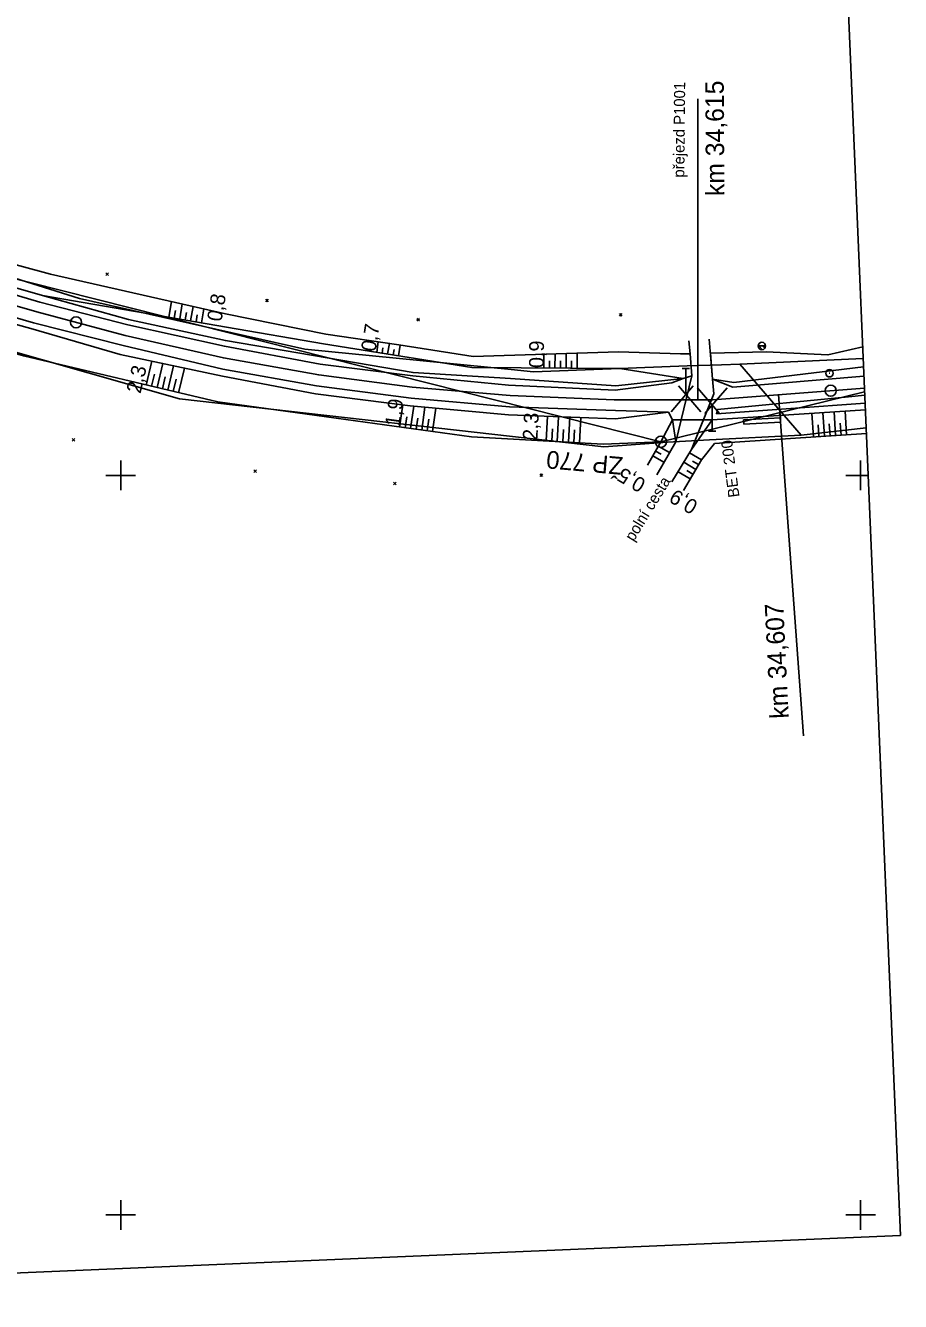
# Model space of a CAD drawing. Extents: x -806456 to -805395, y -1150847 to -1150506.
# Drawn here: x -805512.9 to -805394.6, y -1150811.7 to -1150639.2 of the extents above; entities that cross this region are included whole.
import ezdxf

# ---------------------------------------------------------------- set-up
doc = ezdxf.new("R2010")
doc.units = 0
for name, color, linetype in [('0381KM032-037P - Vrstva 1', 7, 'Continuous'), ('0381KM032-037P - Vrstva 19', 7, 'Continuous'), ('0381KM032-037P - Vrstva 36', 7, 'Continuous'), ('0381KM032-037P - Vrstva 4', 7, 'Continuous'), ('0381KM032-037P - Vrstva 48', 7, 'Continuous'), ('0381KM032-037P - Vrstva 49', 7, 'Continuous'), ('0381KM032-037P - Vrstva 51', 7, 'Continuous'), ('0381KM032-037P - Vrstva 55', 7, 'Continuous'), ('0381KM032-037P - Vrstva 7', 7, 'Continuous'), ('0381KM032-037P - Vrstva 9', 7, 'Continuous'), ('formát', 7, 'Continuous'), ('hran DP - hran DP', 7, 'Continuous'), ('krizky_1000 - Vrstva 1', 7, 'Continuous'), ('vyt_sit - polygon', 7, 'Continuous'), ('vyt_sit - stávající', 7, 'Continuous')]:
    doc.layers.add(name, color=color, linetype=linetype)

msp = doc.modelspace()

# ---------------------------------------------------------------- linework, layer by layer
at = {"layer": '0381KM032-037P - Vrstva 1'}
for points in [[(-805499.4, -1150681.08), (-805511.35, -1150677.89), (-805524.48, -1150674.12), (-805529.81, -1150672.54)], [(-805399.47, -1150688.2), (-805419.96, -1150689.78), (-805423.96, -1150689.8), (-805433.29, -1150689.8), (-805447.38, -1150689.21), (-805460.61, -1150688.07), (-805473.24, -1150686.41), (-805486.12, -1150684.11), (-805499.4, -1150681.08)]]:
    msp.add_lwpolyline(points, dxfattribs=at)
at = {"layer": '0381KM032-037P - Vrstva 19'}
msp.add_line((-805425.41, -1150692.47), (-805420.07, -1150692.47), dxfattribs=at)
at = {"layer": '0381KM032-037P - Vrstva 36'}
for p, q in [((-805413.84, -1150682.5), (-805412.84, -1150682.5)), ((-805412.84, -1150682.5), (-805413.84, -1150682.5)), ((-805413.28, -1150683), (-805413.77, -1150682.5)), ((-805412.94, -1150682.8), (-805413.24, -1150682.5))]:
    msp.add_line(p, q, dxfattribs=at)
msp.add_circle((-805413.34, -1150682.5), 0.503, dxfattribs=at)
msp.add_arc((-805413.34, -1150682.5), 0.503, 180, 0, dxfattribs=at)
at = {"layer": '0381KM032-037P - Vrstva 4'}
for p, q in [((-805421.99, -1150689.77), (-805421.99, -1150649.07)), ((-805423.11, -1150685.55), (-805424.11, -1150685.55)), ((-805423.61, -1150685.55), (-805423.61, -1150689.05)), ((-805422.61, -1150687.9), (-805425.61, -1150691.4)), ((-805421.61, -1150691.4), (-805424.61, -1150687.9)), ((-805422.05, -1150688.15), (-805419.05, -1150691.65)), ((-805421.05, -1150691.65), (-805418.05, -1150688.15)), ((-805423.96, -1150689.8), (-805419.82, -1150689.74)), ((-805420.05, -1150694), (-805420.05, -1150690.5)), ((-805420.55, -1150694), (-805419.55, -1150694))]:
    msp.add_line(p, q, dxfattribs=at)
for points in [[(-805485.85, -1150681.76), (-805498.96, -1150678.92), (-805510.6, -1150675.66), (-805525.22, -1150671.48), (-805544.53, -1150665.72), (-805562.31, -1150661.11), (-805574.56, -1150658.15), (-805590.74, -1150655.42), (-805602.22, -1150654.14), (-805617.62, -1150652.74), (-805630.08, -1150651.83), (-805647.65, -1150650.8), (-805688.26, -1150650.5)], [(-805423.97, -1150686.92), (-805425.51, -1150687.49), (-805433.17, -1150688.49), (-805447.58, -1150687.79), (-805460.54, -1150686.52), (-805473.03, -1150684.97), (-805486, -1150682.53), (-805499.06, -1150679.64), (-805510.93, -1150676.58), (-805525.41, -1150672.29), (-805545.14, -1150666.47), (-805562.36, -1150661.85), (-805574.71, -1150659.28), (-805590.7, -1150656.46), (-805602.42, -1150654.96), (-805617.57, -1150653.8), (-805630.08, -1150653.28), (-805647.6, -1150652.35), (-805687.98, -1150651.47)], [(-805425.98, -1150691.47), (-805433.13, -1150691.22), (-805447.47, -1150690.71), (-805460.74, -1150689.57), (-805473.54, -1150687.87), (-805486.2, -1150685.62), (-805499.7, -1150682.42), (-805511.82, -1150679.35), (-805526.11, -1150675.23), (-805545.84, -1150669.48), (-805563.16, -1150664.96), (-805575.57, -1150662.2), (-805590.62, -1150659.46), (-805602.86, -1150658.06), (-805617.64, -1150656.78), (-805630.16, -1150656.16), (-805647.73, -1150655.65), (-805688.15, -1150654.42)], [(-805425.41, -1150692.47), (-805425.98, -1150691.47), (-805433.11, -1150692.35), (-805447.61, -1150691.82), (-805460.9, -1150690.59), (-805473.67, -1150688.98), (-805486.26, -1150686.57), (-805500.08, -1150683.65), (-805512.15, -1150680.12), (-805526.27, -1150676.26), (-805545.98, -1150670.57), (-805563.42, -1150665.87), (-805575.79, -1150663.12), (-805590.93, -1150660.59), (-805603.28, -1150659.09), (-805617.92, -1150657.97), (-805630.11, -1150657.32), (-805646.66, -1150657.1), (-805648.58, -1150657.2), (-805687.42, -1150655.93)], [(-805423.97, -1150686.92), (-805433.1, -1150687.91), (-805447.34, -1150686.91), (-805460.49, -1150686.09), (-805485.85, -1150681.76)], [(-805399.6, -1150685.34), (-805417.14, -1150687.42), (-805420, -1150686.97)], [(-805399.54, -1150686.56), (-805417.27, -1150688.09), (-805420, -1150686.97)], [(-805399.43, -1150689.16), (-805401.63, -1150689.36), (-805419.33, -1150691.07), (-805419.49, -1150691.68)], [(-805399.39, -1150690.24), (-805419.49, -1150691.68)]]:
    msp.add_lwpolyline(points, dxfattribs=at)
at = {"layer": '0381KM032-037P - Vrstva 48'}
for p, q in [((-805493.52, -1150678.6), (-805493.15, -1150676.49)), ((-805492.78, -1150678.73), (-805492.6, -1150677.69)), ((-805492.04, -1150678.85), (-805491.69, -1150676.82)), ((-805491.3, -1150678.98), (-805491.13, -1150677.99)), ((-805490.56, -1150679.11), (-805490.22, -1150677.16)), ((-805489.82, -1150679.23), (-805489.66, -1150678.28)), ((-805489.08, -1150679.36), (-805488.76, -1150677.49)), ((-805465.41, -1150683.34), (-805465.19, -1150681.94)), ((-805464.67, -1150683.46), (-805464.56, -1150682.75)), ((-805463.93, -1150683.58), (-805463.7, -1150682.16)), ((-805463.19, -1150683.7), (-805463.07, -1150682.98)), ((-805462.45, -1150683.82), (-805462.22, -1150682.37)), ((-805441.32, -1150685.5), (-805441.3, -1150683.55)), ((-805439.82, -1150685.51), (-805439.8, -1150683.51)), ((-805438.32, -1150685.52), (-805438.3, -1150683.46)), ((-805496.56, -1150687.78), (-805495.8, -1150684.56)), ((-805495.1, -1150688.12), (-805494.33, -1150684.87)), ((-805493.64, -1150688.47), (-805492.86, -1150685.18)), ((-805442.82, -1150685.49), (-805442.8, -1150683.6)), ((-805442.07, -1150685.49), (-805442.06, -1150684.53)), ((-805440.57, -1150685.5), (-805440.56, -1150684.52)), ((-805439.07, -1150685.51), (-805439.06, -1150684.5)), ((-805495.83, -1150687.95), (-805495.45, -1150686.33)), ((-805494.37, -1150688.3), (-805493.98, -1150686.66)), ((-805492.91, -1150688.64), (-805492.52, -1150686.99)), ((-805492.18, -1150688.82), (-805491.39, -1150685.49)), ((-805462.31, -1150693.46), (-805461.89, -1150690.47)), ((-805461.56, -1150693.56), (-805461.35, -1150692.06)), ((-805460.82, -1150693.66), (-805460.4, -1150690.64)), ((-805459.33, -1150693.87), (-805458.91, -1150690.78)), ((-805457.85, -1150694.07), (-805457.41, -1150690.91)), ((-805442.5, -1150695.34), (-805442.32, -1150692.01)), ((-805441, -1150695.43), (-805440.82, -1150692.07)), ((-805439.5, -1150695.51), (-805439.32, -1150692.12)), ((-805438, -1150695.59), (-805437.82, -1150692.18)), ((-805406.38, -1150694.81), (-805406.59, -1150691.59)), ((-805404.88, -1150694.71), (-805405.09, -1150691.49)), ((-805403.39, -1150694.62), (-805403.59, -1150691.39)), ((-805401.89, -1150694.52), (-805402.09, -1150691.3)), ((-805460.08, -1150693.77), (-805459.86, -1150692.24)), ((-805458.59, -1150693.97), (-805458.38, -1150692.41)), ((-805441.75, -1150695.39), (-805441.66, -1150693.71)), ((-805440.25, -1150695.47), (-805440.16, -1150693.78)), ((-805438.75, -1150695.55), (-805438.66, -1150693.85)), ((-805405.63, -1150694.76), (-805405.73, -1150693.15)), ((-805404.13, -1150694.66), (-805404.24, -1150693.05)), ((-805402.64, -1150694.57), (-805402.74, -1150692.96)), ((-805428.08, -1150697.36), (-805426.58, -1150698.22)), ((-805427.71, -1150696.71), (-805426.96, -1150697.14)), ((-805427.34, -1150696.06), (-805425.83, -1150696.92)), ((-805421.51, -1150697.9), (-805423.11, -1150696.95)), ((-805422.27, -1150699.19), (-805423.9, -1150698.22)), ((-805421.89, -1150698.54), (-805422.7, -1150698.06)), ((-805423.04, -1150700.48), (-805424.68, -1150699.5)), ((-805422.66, -1150699.83), (-805423.47, -1150699.35))]:
    msp.add_line(p, q, dxfattribs=at)
at = {"layer": '0381KM032-037P - Vrstva 49'}
for p, q in [((-805501.66, -1150672.97), (-805502.01, -1150672.62)), ((-805501.66, -1150672.62), (-805502.01, -1150672.97)), ((-805480.06, -1150676.54), (-805480.41, -1150676.19)), ((-805480.06, -1150676.19), (-805480.41, -1150676.54)), ((-805432.26, -1150678.45), (-805432.61, -1150678.1)), ((-805432.26, -1150678.1), (-805432.61, -1150678.45)), ((-805459.62, -1150679.12), (-805459.97, -1150678.77)), ((-805459.62, -1150678.77), (-805459.97, -1150679.12)), ((-805426.99, -1150695.45), (-805425.41, -1150692.47)), ((-805506.23, -1150695.39), (-805506.58, -1150695.03)), ((-805506.23, -1150695.03), (-805506.58, -1150695.39)), ((-805481.65, -1150699.61), (-805482, -1150699.26)), ((-805481.65, -1150699.26), (-805482, -1150699.61)), ((-805442.98, -1150700.16), (-805443.33, -1150699.81)), ((-805442.98, -1150699.81), (-805443.33, -1150700.16)), ((-805462.79, -1150701.28), (-805463.14, -1150700.93)), ((-805462.79, -1150700.93), (-805463.14, -1150701.28))]:
    msp.add_line(p, q, dxfattribs=at)
for points in [[(-805423.97, -1150686.92), (-805433.1, -1150687.91), (-805447.34, -1150686.91), (-805460.49, -1150686.09), (-805485.85, -1150681.76), (-805498.96, -1150678.92), (-805510.6, -1150675.66), (-805525.22, -1150671.48), (-805544.53, -1150665.72), (-805562.31, -1150661.11), (-805571.99, -1150658.79), (-805574.56, -1150658.15), (-805590.74, -1150655.42), (-805602.22, -1150654.14), (-805617.62, -1150652.74), (-805630.08, -1150651.83), (-805647.65, -1150650.8), (-805688.26, -1150650.5)], [(-805424.36, -1150683.57), (-805432.74, -1150683.28), (-805452.35, -1150683.91), (-805462.43, -1150682.34), (-805472.3, -1150680.9), (-805485.84, -1150678.15), (-805509.51, -1150672.79), (-805524.62, -1150668.67), (-805544.15, -1150662.92), (-805562.19, -1150658.51), (-805574.34, -1150655.56), (-805587.56, -1150653.68), (-805602.19, -1150651.94)], [(-805425.41, -1150692.47), (-805425.98, -1150691.47), (-805433.11, -1150692.35), (-805447.61, -1150691.82), (-805460.9, -1150690.59), (-805473.67, -1150688.98), (-805486.26, -1150686.57), (-805500.08, -1150683.65), (-805512.15, -1150680.12), (-805526.27, -1150676.26), (-805545.98, -1150670.57), (-805563.42, -1150665.87), (-805575.79, -1150663.12), (-805590.93, -1150660.59), (-805603.28, -1150659.09), (-805617.92, -1150657.97), (-805630.11, -1150657.32), (-805646.15, -1150657.11), (-805646.27, -1150657.1), (-805646.57, -1150657.13), (-805646.66, -1150657.1), (-805648.58, -1150657.2), (-805687.42, -1150655.93)], [(-805428.8, -1150698.61), (-805426.99, -1150695.45), (-805434.79, -1150695.76), (-805452.59, -1150694.8), (-805474.79, -1150691.73), (-805486.9, -1150690.07), (-805513.13, -1150683.83), (-805526.69, -1150679.91), (-805538.18, -1150675.92), (-805547.05, -1150672.92), (-805563.97, -1150668.42), (-805576.87, -1150665.35), (-805586.81, -1150663.24), (-805590.73, -1150662.74), (-805601.92, -1150661.35), (-805629.88, -1150659.22), (-805648.74, -1150658.99), (-805687.58, -1150660.02)], [(-805422.8, -1150686.53), (-805423.97, -1150686.92), (-805432.55, -1150685.56), (-805452.56, -1150685.41), (-805472.6, -1150682.19), (-805485.72, -1150679.94), (-805510.6, -1150675.66)], [(-805422.8, -1150686.53), (-805423.05, -1150683.54), (-805424.36, -1150683.57)], [(-805412.74, -1150683.31), (-805420.31, -1150683.48), (-805420, -1150686.97)], [(-805412.74, -1150683.31), (-805404.41, -1150683.71), (-805399.71, -1150682.62)], [(-805420, -1150686.97), (-805417.14, -1150687.42), (-805399.6, -1150685.34)], [(-805420.07, -1150692.47), (-805399.35, -1150691.12)], [(-805427.56, -1150699.92), (-805424.99, -1150695.46), (-805425.41, -1150692.47)], [(-805420.07, -1150692.47), (-805422.84, -1150696.5), (-805425.52, -1150700.88)], [(-805419.74, -1150695.67), (-805399.21, -1150694.35)], [(-805423.96, -1150702.03), (-805421.5, -1150697.89), (-805419.74, -1150695.67)]]:
    msp.add_lwpolyline(points, dxfattribs=at)
at = {"layer": '0381KM032-037P - Vrstva 51'}
for points in [[(-805425.52, -1150700.88), (-805422.84, -1150696.5), (-805419.83, -1150688.97), (-805420, -1150686.97), (-805420.48, -1150681.6)], [(-805422.8, -1150686.53), (-805423.05, -1150683.54), (-805423.2, -1150681.79)], [(-805422.8, -1150686.53), (-805424.99, -1150695.46), (-805427.56, -1150699.92)]]:
    msp.add_lwpolyline(points, dxfattribs=at)
at = {"layer": '0381KM032-037P - Vrstva 55'}
msp.add_line((-805416.34, -1150684.94), (-805408.01, -1150694.56), dxfattribs=at)
at = {"layer": '0381KM032-037P - Vrstva 7'}
msp.add_line((-805404.26, -1150686.19), (-805404.16, -1150686.19), dxfattribs=at)
for centre, radius in [((-805506.04, -1150679.31), 0.75), ((-805404.21, -1150686.19), 0.5), ((-805404.03, -1150688.55), 0.75)]:
    msp.add_circle(centre, radius, dxfattribs=at)
at = {"layer": '0381KM032-037P - Vrstva 9'}
for p, q in [((-805411.08, -1150689.08), (-805407.73, -1150735.22)), ((-805410.84, -1150692.23), (-805410.86, -1150691.64)), ((-805410.84, -1150692.23), (-805415.83, -1150692.47)), ((-805415.83, -1150692.47), (-805415.8, -1150693.06)), ((-805415.8, -1150693.06), (-805410.81, -1150692.82)), ((-805410.81, -1150692.82), (-805410.84, -1150692.23))]:
    msp.add_line(p, q, dxfattribs=at)
at = {"layer": 'formát'}
for p, q in [((-805407.21, -1150506.06), (-805394.61, -1150802.8)), ((-805394.61, -1150802.8), (-805604.42, -1150811.7))]:
    msp.add_line(p, q, dxfattribs=at)
at = {"layer": 'hran DP - hran DP'}
for p, q in [((-805522.57, -1150670.78), (-805505.56, -1150676.07)), ((-805505.56, -1150676.07), (-805488.96, -1150679.81)), ((-805492.06, -1150689.65), (-805525.6, -1150680.1)), ((-805488.96, -1150679.81), (-805475.13, -1150682.93)), ((-805475.13, -1150682.93), (-805447.24, -1150685.68)), ((-805433.7, -1150685.59), (-805423.42, -1150685.2)), ((-805423.42, -1150685.2), (-805418.81, -1150685.03)), ((-805418.81, -1150685.03), (-805416.34, -1150684.94)), ((-805416.34, -1150684.94), (-805399.64, -1150684.18)), ((-805447.24, -1150685.68), (-805444.22, -1150685.98)), ((-805444.22, -1150685.98), (-805433.7, -1150685.59)), ((-805434.71, -1150696.14), (-805492.06, -1150689.65)), ((-805399.25, -1150693.56), (-805408.01, -1150694.56)), ((-805426.08, -1150695.49), (-805434.71, -1150696.14)), ((-805420.42, -1150695.2), (-805426.08, -1150695.49)), ((-805408.01, -1150694.56), (-805420.42, -1150695.2))]:
    msp.add_line(p, q, dxfattribs=at)
at = {"layer": 'krizky_1000 - Vrstva 1'}
for points in [[(-805500, -1150698), (-805500, -1150702)], [(-805400, -1150698), (-805400, -1150702)], [(-805502, -1150700), (-805498, -1150700)], [(-805402, -1150700), (-805398.97, -1150700)], [(-805500, -1150798), (-805500, -1150802)], [(-805400, -1150798), (-805400, -1150802)], [(-805502, -1150800), (-805498, -1150800)], [(-805402, -1150800), (-805398, -1150800)]]:
    msp.add_lwpolyline(points, dxfattribs=at)
at = {"layer": 'vyt_sit - polygon'}
for p, q in [((-805585.64, -1150655.42), (-805426.99, -1150695.45)), ((-805426.99, -1150695.45), (-805399.45, -1150688.7))]:
    msp.add_line(p, q, dxfattribs=at)
at = {"layer": 'vyt_sit - stávající'}
msp.add_line((-805427.04, -1150695.45), (-805426.94, -1150695.45), dxfattribs=at)
msp.add_circle((-805426.99, -1150695.45), 0.756, dxfattribs=at)

# ---------------------------------------------------------------- texts
at = {"layer": '0381KM032-037P - Vrstva 19'}
msp.add_text('BET 200', height=1.5, rotation=97.5063, dxfattribs=at).set_placement((-805416.36, -1150702.88))
at = {"layer": '0381KM032-037P - Vrstva 4'}
for s, height, rotation, p in [('přejezd P1001', 1.5, 89.4547, (-805423.83, -1150659.74)), ('km 34,615', 2.5, 90.3142, (-805418.41, -1150662.22))]:
    msp.add_text(s, height=height, rotation=rotation, dxfattribs=at).set_placement(p)
at = {"layer": '0381KM032-037P - Vrstva 48'}
for s, rotation, p in [('0,8', 80.2414, (-805486.4, -1150679.29)), ('0,7', 80.8528, (-805465.58, -1150683.35)), ('0,9', 89.5678, (-805442.82, -1150685.49)), ('2,3', 76.6332, (-805497.34, -1150689.02)), ('1,9', 82.1252, (-805462.31, -1150693.46)), ('2,3', 86.8943, (-805443.69, -1150695.28)), ('0,5', 150.2278, (-805428.88, -1150700.69)), ('0,9', 149.2587, (-805421.83, -1150703.66))]:
    msp.add_text(s, height=2, rotation=rotation, dxfattribs=at).set_placement(p)
at = {"layer": '0381KM032-037P - Vrstva 51'}
msp.add_text('polní cesta', height=1.5, rotation=58.5387, dxfattribs=at).set_placement((-805430.69, -1150709.03))
at = {"layer": '0381KM032-037P - Vrstva 9'}
msp.add_text('km 34,607', height=2.5, rotation=92.7706, dxfattribs=at).set_placement((-805409.71, -1150732.84))
at = {"layer": 'vyt_sit - stávající'}
msp.add_text('ŽP 770', height=2.4, rotation=175, dxfattribs=at).set_placement((-805432.05, -1150697.54))

doc.saveas('drawing.dxf')
